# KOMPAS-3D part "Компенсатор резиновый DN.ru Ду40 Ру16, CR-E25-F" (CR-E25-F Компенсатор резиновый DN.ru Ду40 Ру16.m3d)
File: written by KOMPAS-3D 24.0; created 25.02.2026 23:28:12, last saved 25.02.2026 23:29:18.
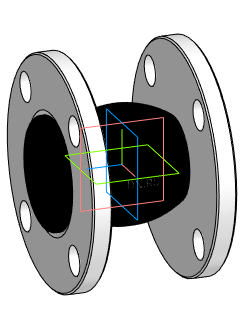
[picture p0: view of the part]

Document properties: Автор: DN.RU; Полное имя файла: D:\PROJECT CAD\DN.RU\...178(4)(ACTUALE). CR-E25-F Компенсатор резиновый DN.ru Ру10-16\DN40_PN16\CR-E25-F Компенсатор резиновый DN.ru Ду40 Ру16.m3d

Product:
- Body: Твердое тело2  | qty 1
    Масса: 3.467288
- Part/product: Компенсатор резиновый DN.ru Ду40 Ру16  | designation CR-E25-F
    Масса: 3.68
    Раздел спецификации: Прочие изделия
    Комментарий: D140-02172
    Примечание: D140-02172
    additional columns: Типовые

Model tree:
1. Твердое тело2  (labels: Твердое тело2)

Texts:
  CR-E25-F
